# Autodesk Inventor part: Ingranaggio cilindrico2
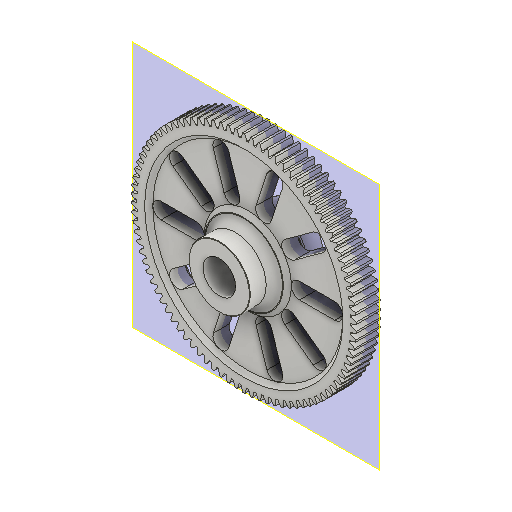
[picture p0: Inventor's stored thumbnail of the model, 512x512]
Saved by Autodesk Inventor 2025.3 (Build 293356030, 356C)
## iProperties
CustomPartVersion: 1
Created: 2026-05
Part Number: Ingranaggio cilindrico2
Material: Acciaio inossidabile
Document SubType Name: Modeling
Designer: R5800u
Categories: <?xml version="1.0" encoding="UTF-16"?> <MemberInstance><Categories><FamilyTemplate><FamilyTemplateParameter ValueType="xs:double" Id="1" ObjectReferenceKey="da
Density: 8 g/cm^3
Appearance: Acciaio
Author: R5800u
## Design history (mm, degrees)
sketch "Sketch1"
  geometry: C1 r 138 at (0, 0)
  constraints: 1 centre point
  dimensions: "d0" = 276 diameter of C1 (= da_da)
extrude "Extrusion1" new body sketch "Sketch1" distance "d1" = 30 (= da_b); taper "d2" = 0 deg
workplane "Work Plane2"
feature "Diametro primitivo" dims "d4" = 10, "d5" = 0
workplane "Work Plane8"
workplane "Work Plane9"
feature "Ingranaggio cilindrico" dims "da_b" = 30, "da_d" = 270, "da_aw" = 162, "da_da" = 276, "da_df" = 262.5, "da_dw" = 270, angle "da_beta" = 0 deg, "da_lefttooth" = 0, "da_righttooth" = 0
sketch "Schizzo3"
  geometry: A1 r 131.25 centre (0, 0) between (-48.103, 122.117) and (-50.227, 121.259) reference; 2 further points
  constraints: 1 coincident
hole "Foro1" sketch "Schizzo3" at (0, 0) diameter "d49" = 40; stored, may be unused: countersink angle "d53" = 90 deg, drill point angle "d55" = 118 deg; dims "d50" = 6, "d51" = 4, "d52" = 2, "d54" = 10
sketch "Schizzo4"
  geometry: C1 r 37.5 at (0, 0); C2 r 20 at (0, 0) reference; 1 further point
  constraints: 1 centre point, 1 coincident
  dimensions: "d56" = 75 diameter of C1
extrude "Estrusione2" join sketch "Schizzo4" distance "d57" = 30; taper "d58" = 0 deg
fillet "Raccordo1" dims "d59" = 10
node "Piano di lavoro11"
mirror "Speculare1"
chamfer "Smusso1" distance "d60" = 0.5; stored, may be unused: second distance "d61" = 2, angle "d62" = 45 deg
sketch "Schizzo5"
  geometry: L1 (106.579, 0)-(63.421, 0); L2 (106.579, 10)-(63.421, 10); L3 (63.421, -10)-(106.579, -10); A1 r 10 centre (106.579, 0) between (106.579, -10) and (106.579, 10); A2 r 10 centre (63.421, 0) between (63.421, 10) and (63.421, -10); 2 further points
  constraints: 8 end point, 4 point on circle, 4 tangent, 2 centre point, 1 horizontal, 1 midpoint, 1 parallel
  dimensions: "d63" = 20 diameter of A2; "d64" = 85 distance of point (0, 0) point (85, 0)
extrude "Estrusione3" cut sketch "Schizzo5" extent not by distance; stored distance "d65" = 0; taper "d66" = 0 deg
pattern_circular "Serie circolare1" dims angle "d68" = 360 deg
sketch "Schizzo6"
  geometry: C1 r 37.5 at (0, 0) reference; C2 r 116.579 at (0, 0); C3 r 20 at (0, 0) reference; C4 r 53.421 at (0, 0); A1 r 10 centre (63.421, 0) between (63.421, 10) and (63.421, -10) reference; 1 further point
  constraints: 2 centre point, 2 coincident, 1 tangent
extrude "Estrusione4" cut sketch "Schizzo6" distance "d70" = 5; taper "d71" = 0 deg
mirror "Speculare2"
chamfer "Smusso2" distance "d74" = 5; stored, may be unused: second distance "d75" = 2, angle "d76" = 45 deg
body "Solid1"
sketch "Sketch2"
  geometry: C1 r 138 at (0, 0) reference; C2 r 135 at (0, 0)
  constraints: 1 centre point, 1 coincident
  dimensions: "d3" = 270 diameter of C2 (= da_d)
body "Srf1"
other parameters: "d16" = 162 (= da_aw), "d17" = 0, "d34" = 2 deg (computed from da_z), "d39" = 0, "d41" = 0, "d43" = 162 (= da_aw), "d46" = 162 (= da_aw), "d47" = 0, "d48" = 0
